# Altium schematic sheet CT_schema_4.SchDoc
size 321 x 309 mm
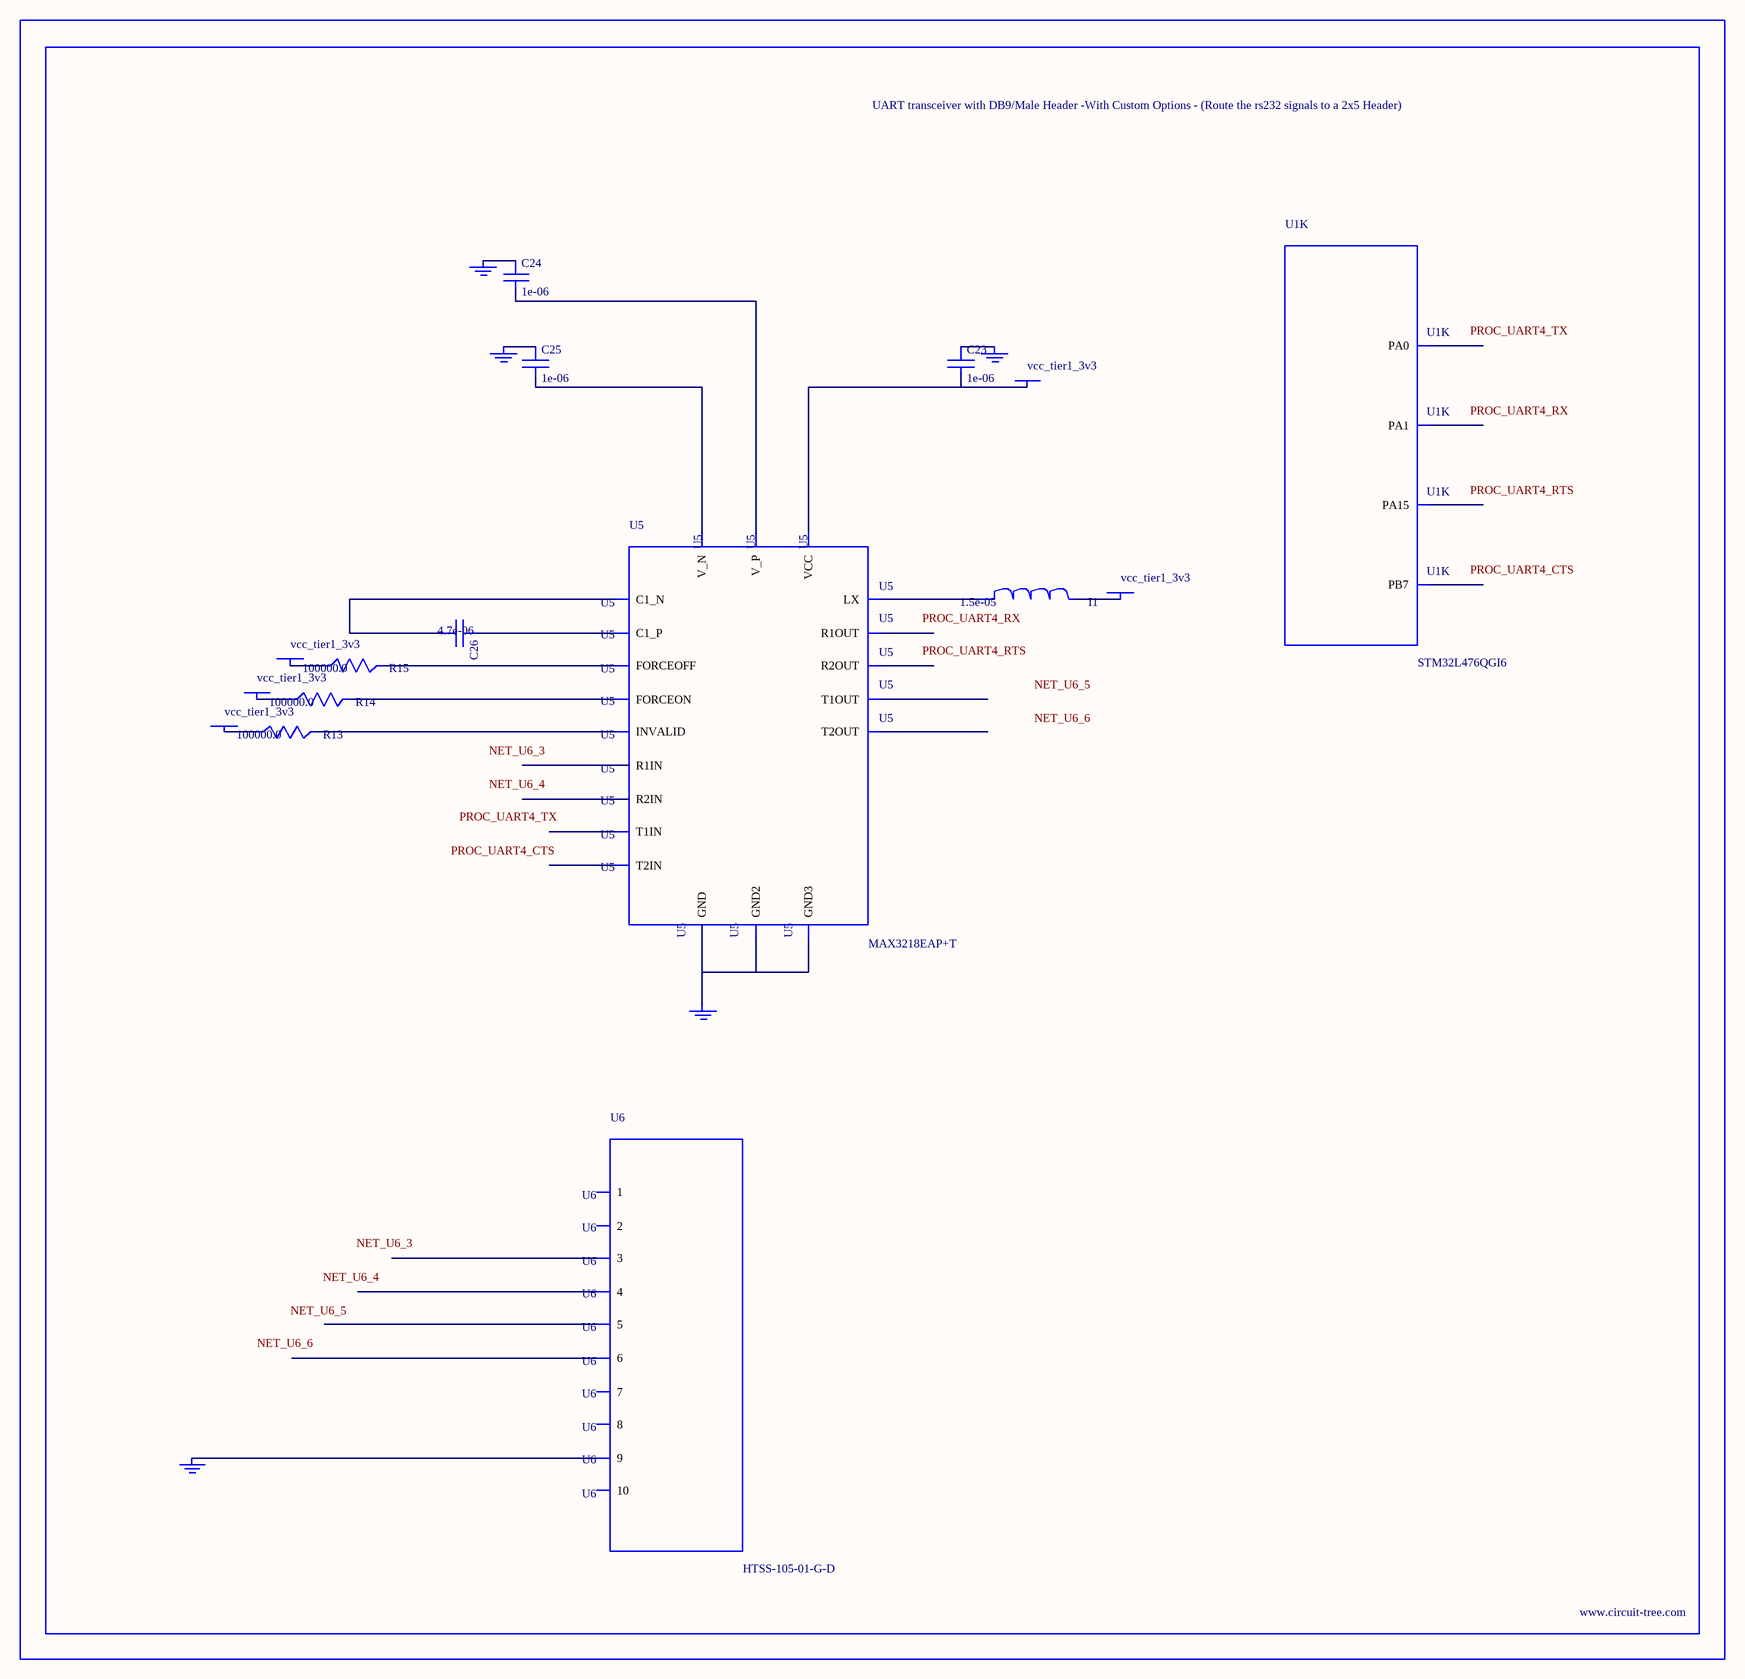
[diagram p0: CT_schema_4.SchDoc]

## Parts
BORDER3  (no value)
C23  1e-06  [C0603]
C24  1e-06  [C0603]
C25  1e-06  [C0603]
C26  4.7e-06  [C0805]
GND_INSTANCE_3_0  (no value)
GND_INSTANCE_3_1  (no value)
GND_INSTANCE_3_2  (no value)
GND_INSTANCE_3_3  (no value)
GND_INSTANCE_3_4  (no value)
I1  1.5e-05  [L1210]
POWER_INSTANCE_3_0  vcc_tier1_3v3
POWER_INSTANCE_3_1  vcc_tier1_3v3
POWER_INSTANCE_3_2  vcc_tier1_3v3
POWER_INSTANCE_3_3  vcc_tier1_3v3
POWER_INSTANCE_3_4  vcc_tier1_3v3
R13  100000.0  [R0603]
R14  100000.0  [R0603]
R15  100000.0  [R0603]
U1  STM32L476QGI6  [UFBGA132]  (part K of 12)
U5  MAX3218EAP+T  [SSOP-20]
U6  HTSS-105-01-G-D  [HTSS-105-01-G-D]

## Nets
NetC23_1: C23.1 GND_INSTANCE_3_0.0(GND)
NetC23_2: C23.2 POWER_INSTANCE_3_4.0(PWR) U5.6(VCC)
NetC24_1: C24.1 GND_INSTANCE_3_2.0(GND)
NetC24_2: C24.2 U5.19(V_P)
NetC25_1: C25.1 GND_INSTANCE_3_1.0(GND)
NetC25_2: C25.2 U5.15(V_N)
NetC26_1: C26.1 U5.18(C1_P)
NetC26_2: C26.2 U5.16(C1_N)
NetGND_INSTANCE_3_3_0: GND_INSTANCE_3_3.0(GND) U5.5(GND) U5.17(GND2) U5.20(GND3)
NetGND_INSTANCE_3_4_0: GND_INSTANCE_3_4.0(GND) U6.9
NetI1_1: I1.1 U5.1(LX)
NetI1_2: I1.2 POWER_INSTANCE_3_0.0(PWR)
NetPOWER_INSTANCE_3_1_0: POWER_INSTANCE_3_1.0(PWR) R13.1
NetPOWER_INSTANCE_3_2_0: POWER_INSTANCE_3_2.0(PWR) R14.1
NetPOWER_INSTANCE_3_3_0: POWER_INSTANCE_3_3.0(PWR) R15.1
NetR13_2: R13.2 U5.2(INVALID)
NetR14_2: R14.2 U5.3(FORCEON)
NetR15_2: R15.2 U5.4(FORCEOFF)

Not connected (* = marked no-connect by the designer): U1 A9(PA15) B4(PB7) L2(PA0) M2(PA1); U5 7(T1IN) 8(T2IN) 9(R1OUT) 10(R2OUT) 11(R2IN) 12(R1IN) 13(T2OUT) 14(T1OUT); U6 1 2 3 4 5 6 7 8 10

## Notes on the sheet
- Labels drawn without touching a wire or pin: NET_U6_3, NET_U6_4, NET_U6_5, NET_U6_6, PROC_UART4_CTS, PROC_UART4_RTS, PROC_UART4_RX, PROC_UART4_TX

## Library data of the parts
BORDER3 = BORDER_PAGE3
C23-C25 = C0603C105K3RACTU
C26 = C0805C475K4RACTU
GND_INSTANCE_3_0-GND_INSTANCE_3_4 = GND
I1 = L1210R150MDWIT
POWER_INSTANCE_3_0-POWER_INSTANCE_3_4 = PWR
R13-R15 = RC0603JR-07100KL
